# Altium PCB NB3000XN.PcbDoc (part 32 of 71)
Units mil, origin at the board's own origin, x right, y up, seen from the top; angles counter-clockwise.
Board outline 9527.56 x 6929.77 mil, 6 copper layers (Top Layer, GND+SHIELD, MidLayer1, MidLayer2, P2 - 3V3+5V0, Bottom Layer), stack 62.375 mil thick; 832 components, 1027 nets, 4655 pads, 4981 vias.
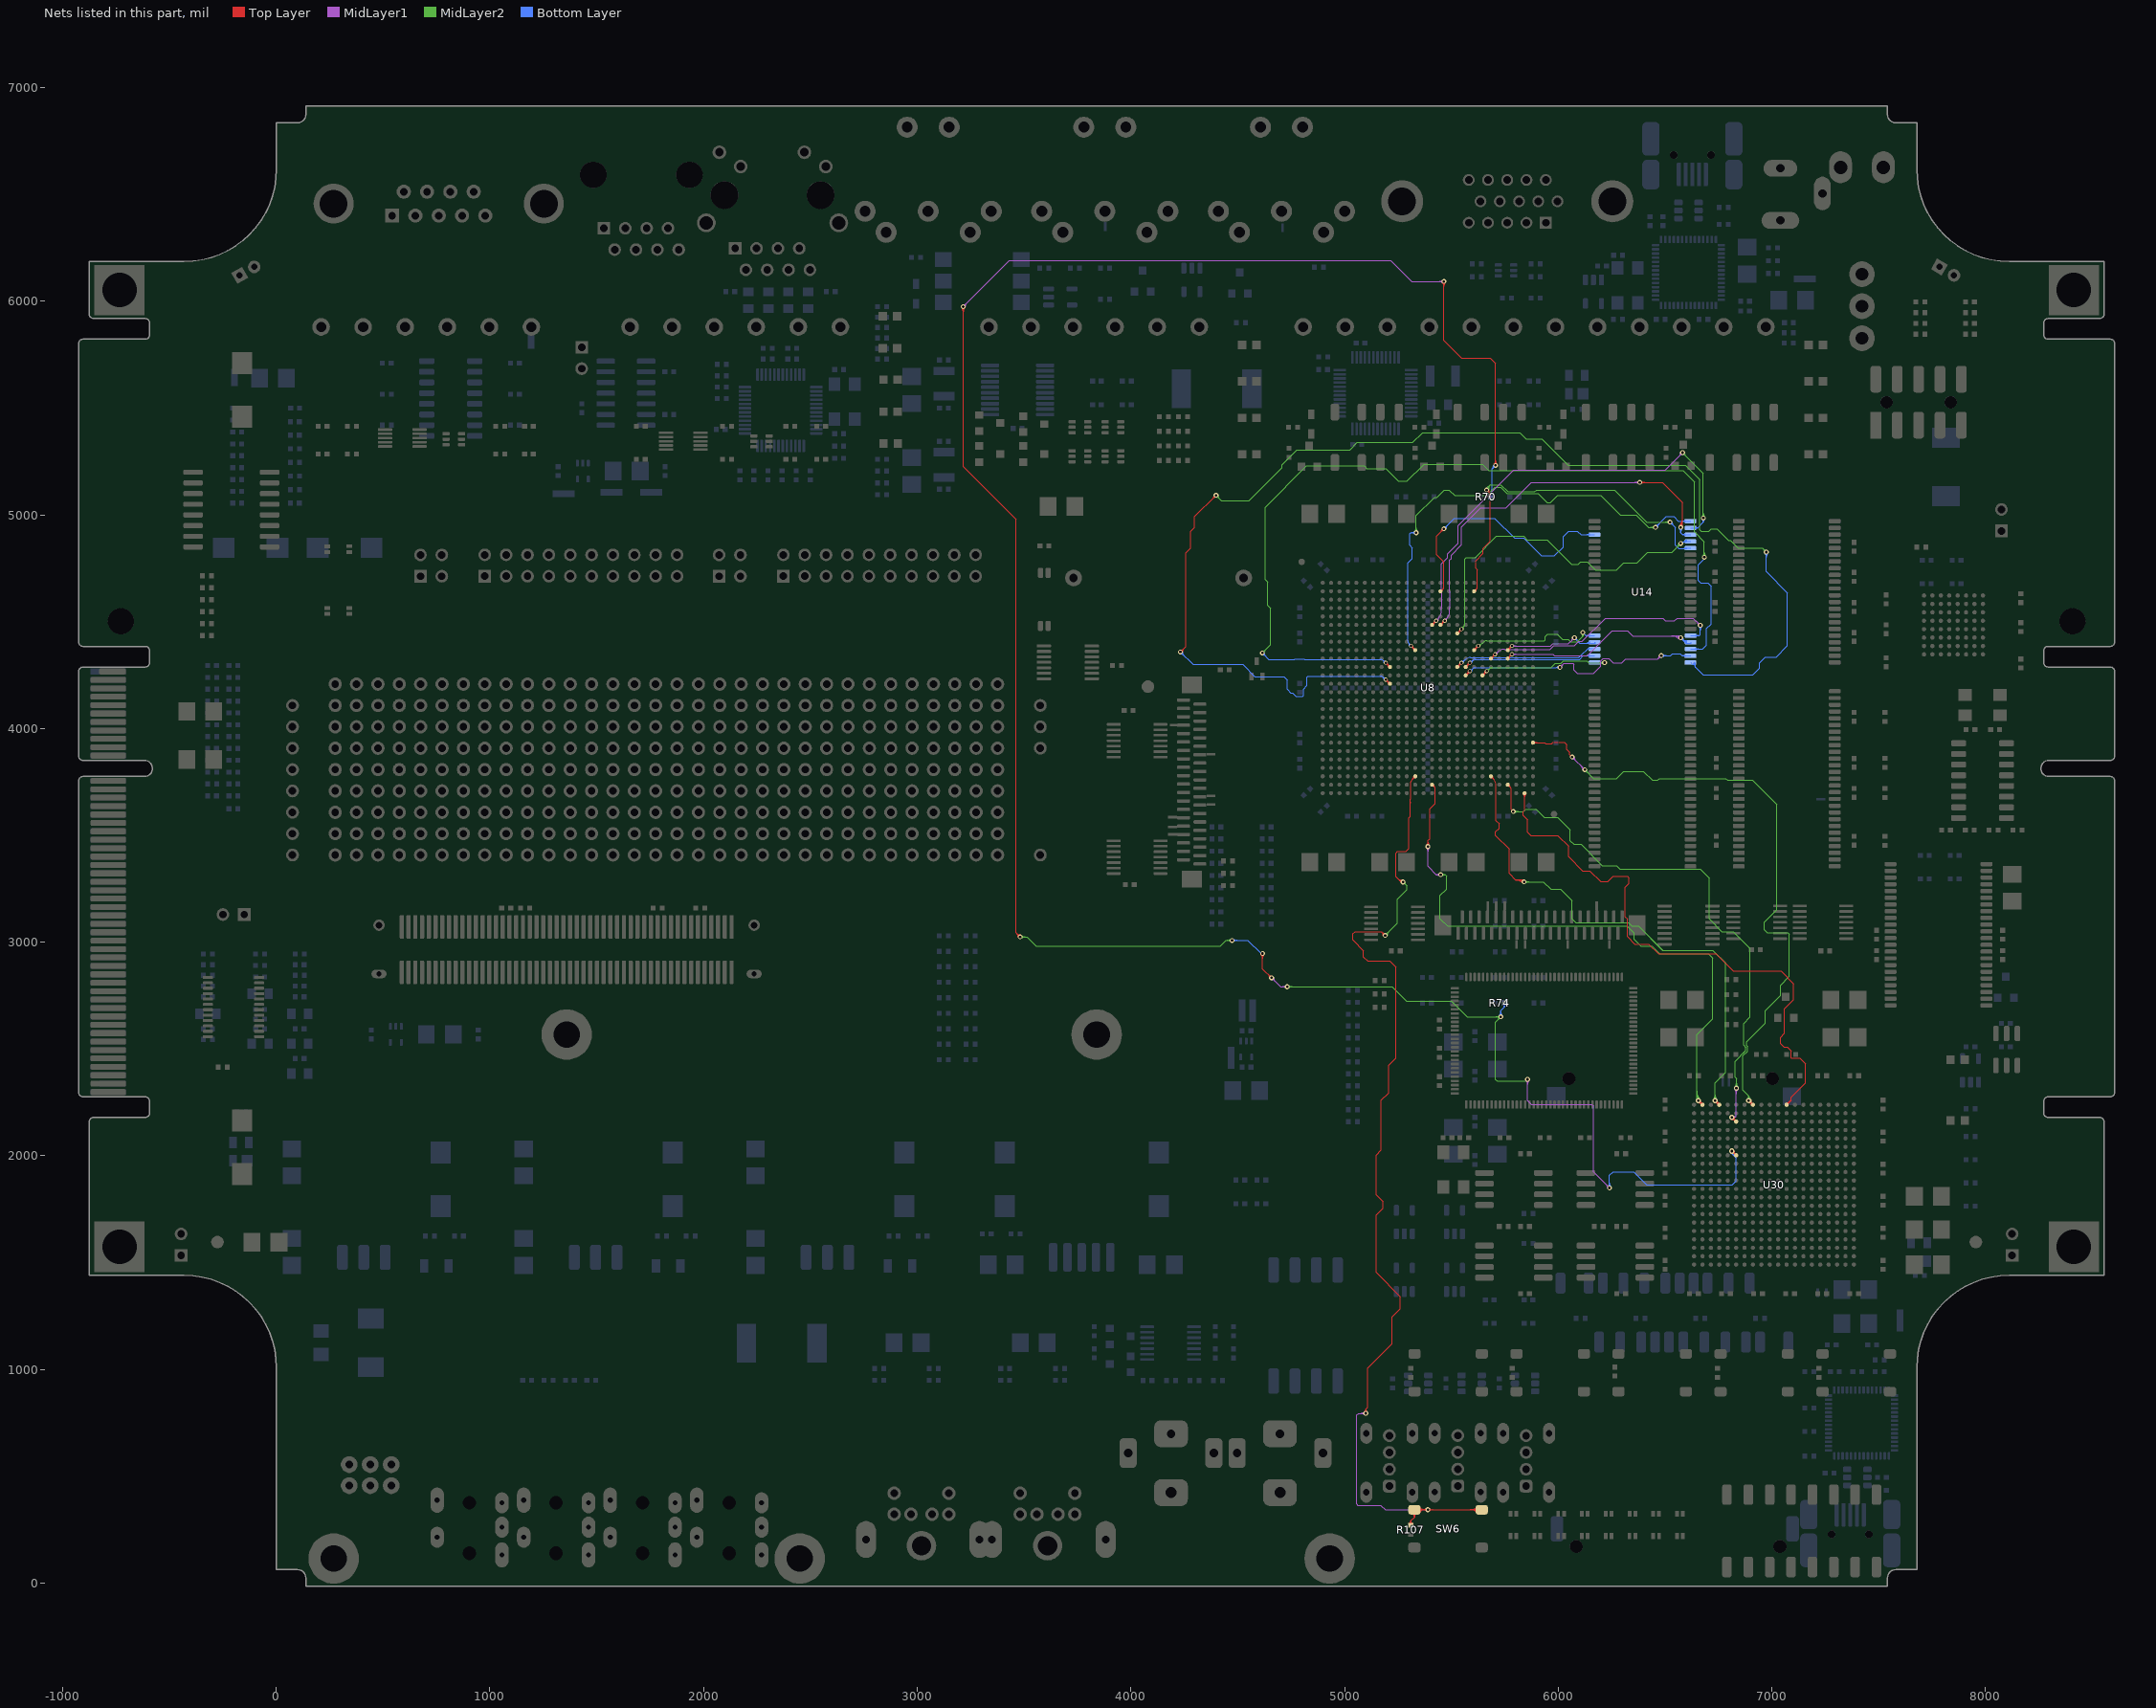
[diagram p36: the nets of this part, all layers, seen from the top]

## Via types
v1: diameter 23, hole 11.81, Top Layer to Bottom Layer, 3672 vias
v2: diameter 26, hole 11.81, Top Layer to Bottom Layer, 461 vias
v3: diameter 19, hole 11.81, Top Layer to Bottom Layer, tented both sides, 396 vias
v4: diameter 23.62, hole 11.81, Top Layer to Bottom Layer, 288 vias
v5: diameter 20, hole 11.81, Top Layer to Bottom Layer, 91 vias
v6: diameter 23, hole 11.81, Top Layer to Bottom Layer, tented both sides, 50 vias
v7: diameter 31, hole 11.81, Top Layer to Bottom Layer, 15 vias
v8: diameter 27.56, hole 11.81, Top Layer to Bottom Layer, tented both sides, 4 vias
v9: diameter 29, hole 11.81, Top Layer to Bottom Layer, 3 vias
v10: diameter 21, hole 11.81, Top Layer to Bottom Layer, 1 vias

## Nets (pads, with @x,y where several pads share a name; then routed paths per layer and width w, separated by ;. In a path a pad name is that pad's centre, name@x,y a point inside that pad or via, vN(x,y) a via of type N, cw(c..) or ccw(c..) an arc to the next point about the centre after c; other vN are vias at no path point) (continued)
DB_PROGRAM.PROGRAM: R70.1 R74.1 U30.R7 | length 12775.2
  Top Layer w4: v1@3208.47,5968.32 cw(c3192.26,5952.11) 3215.19,5952.11 cw(c3238.13,5952.11) v1@3221.91,5968.32 ; v1@3211.3,5971.15 cw(c3201.91,5961.76) 3215.19,5961.76 cw(c3228.47,5961.76) v1@3219.08,5971.15 ; v1(3215.19,5975.04) 3215.19,5224.81 3461.52,4978.48 3461.52,3045.37 v1(3481.86,3025.04) ; v1@3472.36,3025.04 ccw(c3449.42,3025.04) 3465.64,3041.26 ccw(c3481.86,3057.48) v1@3481.86,3034.54 ; v1@3476.36,3025.04 ccw(c3463.08,3025.04) 3472.47,3034.43 ccw(c3481.86,3043.82) v1@3481.86,3030.54 ; v1@4609.81,2940.66 cw(c4593.59,2924.44) 4616.52,2924.44 cw(c4639.46,2924.44) v1@4623.24,2940.66 ; v1@4612.64,2943.49 cw(c4603.25,2934.1) 4616.52,2934.1 cw(c4629.8,2934.1) v1@4620.41,2943.49 ; v1@4615.19,2947.37 v1(4616.52,2947.37) 4616.52,2875.37 v1(4658.52,2833.37) ; v1@4649.02,2833.37 ccw(c4626.09,2833.37) 4642.31,2849.59 ccw(c4658.52,2865.81) v1@4658.52,2842.87 ; v1@4653.02,2833.37 ccw(c4639.75,2833.37) 4649.14,2842.76 ccw(c4658.52,2852.15) v1@4658.52,2838.87 ; v1@5458.47,6085.99 cw(c5442.26,6069.77) 5465.19,6069.77 cw(c5488.13,6069.77) v1@5471.91,6085.99 ; v1@5461.3,6088.82 cw(c5451.91,6079.43) 5465.19,6079.43 cw(c5478.47,6079.43) v1@5469.08,6088.82 ; v1(5465.19,6092.71) 5465.19,5816.71 5548.52,5733.37 5681.86,5733.37 5706.86,5708.37 v1(5706.86,5232.04) ; v1@5700.14,5238.76 ccw(c5683.92,5254.98) 5706.86,5254.98 ccw(c5729.79,5254.98) v1@5713.57,5238.76 ; v1@5702.97,5235.93 ccw(c5693.58,5245.32) 5706.86,5245.32 ccw(c5720.14,5245.32) v1@5710.75,5235.93
  Top Layer w8: v2@6813.15,2013.48 cw(c6813.15,1991.75) 6828.51,2007.12 cw(c6843.88,2022.48) v2@6822.15,2022.48 ; v2(6813.15,2022.48) U30.R7@6832.83,2002.8 ; U30.R7@6826.99,2002.8 ccw(c6812.89,2002.8) 6822.86,2012.77 ccw(c6832.83,2022.74) U30.R7@6832.83,2008.64
  MidLayer1 w4: v1(3215.19,5975.04) 3431.86,6191.71 5215.19,6191.71 5315.19,6091.71 5465.19,6091.71 v1(5465.19,6092.71) ; v1@3215.19,5980.54 ccw(c3215.19,5993.82) 3224.58,5984.43 ccw(c3233.97,5975.04) v1@3220.69,5975.04 ; v1@3215.19,5984.54 ccw(c3215.19,6007.48) 3231.41,5991.26 ccw(c3247.63,5975.04) v1@3224.69,5975.04 ; v1@4658.52,2823.87 cw(c4658.52,2800.94) 4674.74,2817.16 cw(c4690.96,2833.37) v1@4668.02,2833.37 ; v1@4658.52,2827.87 cw(c4658.52,2814.6) 4667.91,2823.99 cw(c4677.3,2833.37) v1@4664.02,2833.37 ; v1(4658.52,2833.37) 4700.19,2791.71 v1(4731.86,2791.71) ; v1@4725.14,2784.99 ccw(c4708.92,2768.77) 4708.92,2791.71 ccw(c4708.92,2814.64) v1@4725.14,2798.43 ; v1@4727.97,2787.82 ccw(c4718.58,2778.43) 4718.58,2791.71 ccw(c4718.58,2804.99) v1@4727.97,2795.6 ; 5439.84,6091.71 ccw(c5439.84,6118.06) v1@5458.47,6099.43 ; 5444.67,6091.71 cw(c5444.67,6072.19) v1@5458.47,6085.99 ; 5449.5,6091.71 ccw(c5449.5,6108.4) v1@5461.3,6096.6 ; v1@5850.14,2351.66 cw(c5833.92,2335.44) 5856.86,2335.44 cw(c5879.79,2335.44) v1@5863.57,2351.66 ; v1@5852.97,2354.49 cw(c5843.58,2345.1) 5856.86,2345.1 cw(c5870.14,2345.1) v1@5860.75,2354.49 ; v1(5856.86,2358.37) 5856.86,2258.37 5873.52,2241.71 6156.86,2241.71 6165.19,2233.37 6165.19,1925.04 v1(6240.19,1850.04) ; v1@6230.69,1850.04 ccw(c6207.76,1850.04) 6223.97,1866.26 ccw(c6240.19,1882.48) v1@6240.19,1859.54 ; v1@6234.69,1850.04 ccw(c6221.41,1850.04) 6230.8,1859.43 ccw(c6240.19,1868.82) v1@6240.19,1855.54
  MidLayer2 w4: v1(3481.86,3025.04) 3515,3025.04 3557.33,2982.71 4419.33,2982.71 4445,3008.37 v1(4473.52,3008.37) ; v1@3485.75,3021.15 cw(c3495.14,3011.76) 3495.14,3025.04 cw(c3495.14,3038.32) v1@3485.75,3028.93 ; v1@3488.57,3018.32 cw(c3504.79,3002.11) 3504.79,3025.04 cw(c3504.79,3047.98) v1@3488.57,3031.76 ; v1@4466.81,3001.66 ccw(c4450.59,2985.44) 4450.59,3008.37 ccw(c4450.59,3031.31) v1@4466.81,3015.09 ; v1@4469.64,3004.49 ccw(c4460.25,2995.1) 4460.25,3008.37 ccw(c4460.25,3021.65) v1@4469.64,3012.26 ; v1(4731.86,2791.71) 5223.52,2791.71 5290.52,2724.71 5500.29,2724.71 5575.29,2649.71 5683.67,2649.71 5685,2651.04 v1(5731.86,2651.04) 5706.86,2626.04 5706.86,2358.14 5715,2350 5848.48,2350 v1(5856.86,2358.37) ; v1@4735.75,2787.82 cw(c4745.14,2778.43) 4745.14,2791.71 cw(c4745.14,2804.99) v1@4735.75,2795.6 ; v1@4738.57,2784.99 cw(c4754.79,2768.77) 4754.79,2791.71 cw(c4754.79,2814.64) v1@4738.57,2798.43 ; v1@5722.36,2651.04 cw(c5699.42,2651.04) 5715.64,2634.82 cw(c5731.86,2618.61) v1@5731.86,2641.54 ; v1@5725.14,2644.32 ccw(c5708.92,2628.11) 5708.92,2651.04 ccw(c5708.92,2673.98) v1@5725.14,2657.76 ; v1@5726.36,2651.04 cw(c5713.08,2651.04) 5722.47,2641.65 cw(c5731.86,2632.26) v1@5731.86,2645.54 ; v1@5727.97,2647.15 ccw(c5718.58,2637.76) 5718.58,2651.04 ccw(c5718.58,2664.32) v1@5727.97,2654.93
  Bottom Layer w4: v1(4473.52,3008.37) 4547.19,3008.37 4608.19,2947.37 v1(4616.52,2947.37) ; v1@4477.41,3004.49 cw(c4486.8,2995.1) 4486.8,3008.37 cw(c4486.8,3021.65) v1@4477.41,3012.26 ; v1@4480.24,3001.66 cw(c4496.46,2985.44) 4496.46,3008.37 cw(c4496.46,3031.31) v1@4480.24,3015.09 ; R70.1@5677.09,5092.08 ccw(c5645.47,5123.7) 5690.19,5123.7 ; R70.1@5679.92,5089.25 ccw(c5655.13,5114.05) 5690.19,5114.05 ; R70.1@5682.75,5086.42 ccw(c5664.78,5104.39) 5690.19,5104.39 ; R70.1@5683.68,5085 5683.68,5083.37 5690.19,5083.37 5690.19,5085 5690.19,5215.37 v1(5706.86,5232.04) ; v1@5697.36,5232.04 cw(c5674.42,5232.04) 5690.64,5215.82 cw(c5706.86,5199.61) v1@5706.86,5222.54 ; v1@5701.36,5232.04 cw(c5688.08,5232.04) 5697.47,5222.65 cw(c5706.86,5213.26) v1@5706.86,5226.54 ; v1@5725.14,2657.76 ccw(c5708.92,2673.98) 5731.86,2673.98 ccw(c5754.79,2673.98) v1@5738.57,2657.76 ; v1@5727.97,2654.93 ccw(c5718.58,2664.32) 5731.86,2664.32 ccw(c5745.14,2664.32) v1@5735.75,2654.93 ; v1(5731.86,2651.04) 5731.86,2680.05 5748.18,2696.37 ; R74.1@5742.76,2706.93 cw(c5735.2,2696.38) 5748.18,2696.38 ; R74.1@5748.18,2715 5748.18,2696.37 ; R74.1@5753.61,2706.93 ccw(c5761.16,2696.38) 5748.18,2696.38 ; v1@6233.47,1856.76 ccw(c6217.26,1872.98) 6240.19,1872.98 ccw(c6263.13,1872.98) v1@6246.91,1856.76 ; v1@6236.3,1853.93 ccw(c6226.91,1863.32) 6240.19,1863.32 ccw(c6253.47,1863.32) v1@6244.08,1853.93 ; v1(6240.19,1850.04) 6240.19,1908.37 6256.86,1925.04 6353.86,1925.04 6415.19,1863.71 6815.19,1863.71 6832.86,1881.37 6832.86,1990.71 6815.19,2008.37 6815.19,2022.48 v2(6813.15,2022.48) ; v2@6812.24,2022.9 ccw(c6823.51,2017.64) 6814.72,2008.85 ; v2@6815.87,2021.21 ccw(c6829.01,2015.07) 6818.75,2004.81 ; v2@6819.49,2019.52 ccw(c6834.51,2012.5) 6822.79,2000.78 ; v2@6823.12,2017.82 ccw(c6840.01,2009.93) 6826.82,1996.74
DB_RESET: R107.2 SW6.1 SW6.2 U8.AD12 | length 5826.8
  Top Layer w4: v4@5094.05,802.8 ccw(c5084.9,814.81) 5100,814.81 ; v4(5100,795) 5100,814.81 ; v4@5105.95,802.8 cw(c5115.1,814.81) 5100,814.81 ; v1@5180.69,3031.71 ccw(c5157.76,3031.71) 5173.97,3047.93 ccw(c5190.19,3064.14) v1@5190.19,3041.21 ; v1@5184.69,3031.71 ccw(c5171.41,3031.71) 5180.8,3041.1 ccw(c5190.19,3050.49) v1@5190.19,3037.21 ; v1(5190.19,3031.71) 5171.86,3050.04 5050.04,3050.04 5040,3040 5040,3010 5089.52,2960.48 5089.52,2930 5107.52,2912 5211.69,2912 5240.19,2883.5 5240.19,2458.37 5206.86,2425.04 5206.86,2295 5172,2260.14 5172,2027 5147.86,2002.86 5147.86,1818.46 5180,1786.31 5180,1755 5147.86,1722.86 5147.86,1453.46 5260,1341.31 5260,1283.54 5222.69,1246.23 5222.69,1120.62 5107.81,1005.74 5107.81,822.62 5100,814.81 ; 5244.36,3302.54 ccw(c5271.79,3329.97) v1@5273.18,3291.2 ; 5250.85,3296.04 ccw(c5272.24,3317.43) v1@5273.33,3287.2 ; 5257.35,3289.55 ccw(c5272.69,3304.89) v1@5273.47,3283.21 ; v1(5273.52,3281.71) 5265.19,3281.71 5240.19,3306.71 5240.19,3416.71 5248.52,3425.04 5287.19,3425.04 5301.19,3439.04 5301.19,3557 5301.19,3582.31 5307.08,3588.21 5307.08,3651.25 ; R107.2@5303.87,278.2 ccw(c5292.05,291.71) 5310,291.71 ; R107.2@5306.5,275.19 ccw(c5299.76,282.9) 5310,282.9 ccw(c5320.24,282.9) R107.2@5313.5,275.19 ; R107.2@5310,271.18 5310,291.71 ; R107.2@5316.13,278.2 cw(c5327.95,291.71) 5310,291.71 ; SW6.1@5317.21,325.64 cw(c5307.93,308.84) 5327.13,308.84 ; SW6.1@5319.15,329.14 cw(c5311.67,315.61) 5327.13,315.61 cw(c5342.58,315.62) SW6.1@5335.11,329.14 ; U8.AD12@5323.6,3776.61 cw(c5305.88,3776.61) 5318.41,3764.08 ; U8.AD12@5330.94,3769.27 ccw(c5330.94,3751.55) 5318.41,3764.08 ; SW6.1@5337.04,325.64 ccw(c5346.33,308.84) 5327.13,308.84 ; SW6.1@5341.96,334.74 cw(c5363.3,313.4) 5363.3,343.58 cw(c5363.3,373.76) SW6.1@5341.96,352.42 ; SW6.1@5344.79,331.92 cw(c5372.96,303.75) 5372.96,343.58 cw(c5372.96,383.42) SW6.1@5344.79,355.25 ; SW6.1@5347.62,329.09 cw(c5382.62,294.09) 5382.62,343.58 cw(c5382.62,393.07) SW6.1@5347.62,358.08 ; v4@5383.06,336.65 ccw(c5366.31,319.9) 5366.31,343.58 ccw(c5366.31,367.27) v4@5383.06,350.52 ; v4@5385.89,339.47 ccw(c5375.97,329.55) 5375.97,343.58 ccw(c5375.97,357.61) v4@5385.89,347.69 ; v4@5394.11,339.47 cw(c5404.03,329.55) 5404.03,343.58 cw(c5404.03,357.61) v4@5394.11,347.69 ; v4@5396.94,336.65 cw(c5413.69,319.9) 5413.69,343.58 cw(c5413.69,367.27) v4@5396.94,350.52 ; SW6.2@5621.98,329.09 ccw(c5586.99,294.09) 5586.99,343.58 ccw(c5586.99,393.07) SW6.2@5621.98,358.08 ; SW6.2@5624.81,331.92 ccw(c5596.65,303.75) 5596.65,343.58 ccw(c5596.65,383.42) SW6.2@5624.81,355.25 ; SW6.2@5627.64,334.74 ccw(c5606.3,313.4) 5606.3,343.58 ccw(c5606.3,373.76) SW6.2@5627.64,352.42 ; SW6.2@5642.48,343.58 v4(5390,343.58) SW6.1@5327.13,343.58 5327.13,308.83 ; 5307.08,3651.25 5307.08,3657 ; 5307.08,3651.25 5307.08,3655.26 5307.08,3657 ; 5307.08,3657 5307.08,3660 5307.08,3670 5307.08,3736.73 cw(c5345.76,3736.73) 5318.41,3764.08 ; 5310,291.71 5327.13,308.83
  MidLayer1 w4: v4@5093.06,788.06 ccw(c5076.31,771.31) 5076.31,795 ccw(c5076.31,818.69) v4@5093.06,801.94 ; v4@5095.89,790.89 ccw(c5085.97,780.97) 5085.97,795 ccw(c5085.97,809.03) v4@5095.89,799.11 ; v4(5100,795) 5065,795 5056.19,786.19 5056.19,370.12 5061.31,365 5170,365 5191.42,343.58 v4(5390,343.58) ; v4@5383.06,336.65 ccw(c5366.31,319.9) 5366.31,343.58 ccw(c5366.31,367.27) v4@5383.06,350.52 ; v4@5385.89,339.47 ccw(c5375.97,329.55) 5375.97,343.58 ccw(c5375.97,357.61) v4@5385.89,347.69
  MidLayer2 w4: v1(5190.19,3031.71) 5248.52,3090.04 5248.52,3202.1 5292.05,3245.62 5292.05,3263.18 v1(5273.52,3281.71) ; v1@5190.19,3037.21 ccw(c5190.19,3050.49) 5199.58,3041.1 ccw(c5208.97,3031.71) v1@5195.69,3031.71 ; v1@5190.19,3041.21 ccw(c5190.19,3064.14) 5206.41,3047.93 ccw(c5222.63,3031.71) v1@5199.69,3031.71 ; v1@5273.52,3272.21 cw(c5273.52,3249.27) 5289.74,3265.49 cw(c5305.96,3281.71) v1@5283.02,3281.71 ; v1@5273.52,3276.21 cw(c5273.52,3262.93) 5282.91,3272.32 cw(c5292.3,3281.71) v1@5279.02,3281.71
DB_SPI.CLK: U8.AE14 U30.W1 | length 3224.2
  Top Layer w4: v1@5383.47,3454.43 ccw(c5363.6,3474.3) 5391.7,3474.3 ; v1@5386.3,3451.6 ccw(c5373.26,3464.64) 5391.7,3464.64 ; v1(5390.19,3447.71) 5391.7,3449.22 5391.7,3475.86 5399.7,3483.86 5399.7,3624.49 5425.19,3649.98 5425.19,3660 5425.19,3670 5425.19,3717.53 ccw(c5415.04,3717.53) 5422.22,3724.71 ; 5391.7,3466.99 ccw(c5409.47,3466.99) v1@5396.91,3454.43 ; U8.AE14@5409.69,3729.9 cw(c5409.69,3712.17) 5422.22,3724.71 ; U8.AE14@5417.03,3737.24 ccw(c5434.75,3737.24) 5422.22,3724.71
  Top Layer w8: v2@6655.67,2249.7 cw(c6655.67,2227.97) 6671.03,2243.34 cw(c6686.4,2258.7) v2@6664.67,2258.7 ; v2(6655.67,2258.7) U30.W1@6675.35,2239.02 ; U30.W1@6669.51,2239.02 ccw(c6655.41,2239.02) 6665.38,2248.99 ccw(c6675.35,2258.96) U30.W1@6675.35,2244.86
  MidLayer1 w4: v1@5383.47,3440.99 cw(c5367.26,3424.77) 5390.19,3424.77 cw(c5413.13,3424.77) v1@5396.91,3440.99 ; v1@5386.3,3443.82 cw(c5376.91,3434.43) 5390.19,3434.43 cw(c5403.47,3434.43) v1@5394.08,3443.82 ; v1(5390.19,3447.71) 5390.19,3355.06 5429.21,3316.04 ; 5437.8,3316.04 ccw(c5437.8,3326.38) v1@5445.72,3319.73 ; 5438.08,3316.04 cw(c5438.08,3305.74) v1@5445.8,3312.55 ; v1@5442.65,3322.3 cw(c5429.21,3333.6) 5429.21,3316.04 ; v1@5442.8,3309.91 ccw(c5429.21,3297.91) 5429.21,3316.04 ; v1(5449.93,3316.19) 5456.04,3316.19 5456.19,3316.04 5429.21,3316.04
  MidLayer2 w4: v1(5449.93,3316.19) v1@5456.04,3316.19 ; v1@5454.05,3312.55 cw(c5462.12,3305.42) 5462.12,3316.19 cw(c5462.12,3326.97) v1@5454.05,3319.83 ; v1@5456.86,3316.71 v1@5456.34,3316.19 ; v1@5457.05,3309.9 cw(c5471,3297.58) 5471,3316.19 ; v1@5457.05,3322.48 ccw(c5471,3334.81) 5471,3316.19 ; 6322.21,3075.04 6355.96,3041.29 6355.96,3013.6 6386.86,2982.71 6438.94,2982.71 6475.27,2946.37 6702.19,2946.37 6723.52,2925.04 6723.52,2641.71 6648.52,2566.71 6648.52,2258.69 v2(6655.67,2258.7) ; 6323.52,3073.71 6322.19,3075.04 5481.86,3075.04 5447.86,3109.04 5447.86,3195 5447.86,3219.02 5477.19,3248.35 5477.19,3252.71 5477.19,3270 5477.19,3310 5471,3316.19 ; 6648.52,2273.54 ccw(c6670.51,2273.54) v2@6654.96,2257.99 ; 6648.52,2283.19 ccw(c6680.16,2283.19) v2@6657.79,2260.82 ; 6648.52,2292.85 ccw(c6689.82,2292.85) v2@6660.62,2263.65 ; 6648.52,2302.51 ccw(c6699.48,2302.51) v2@6663.45,2266.48 ; v1@5456.04,3316.19 5456.19,3316.04 v1@5456.34,3316.19 ; v1@5456.04,3316.19 v1@5456.34,3316.19 ; v1@5456.34,3316.19 5471,3316.19
DB_SPI.DIN: U8.Y26 U30.N1 | length 3334.4
  Top Layer w4: U8.Y26@5882.13,3934.09 5910,3934.09 5920,3934.09 5937.74,3934.09 5941.84,3930 5969.68,3930 5974.83,3935.15 6029.42,3935.15 6040.02,3924.54 6040.02,3902.83 6053.5,3889.36 6053.5,3878.4 v1(6065.19,3866.71) ; U8.Y26@5887.43,3928.79 cw(c5900.23,3915.99) 5900.23,3934.09 cw(c5900.23,3952.2) U8.Y26@5887.43,3939.4 ; 5899.85,3934.09 ccw(c5899.85,3916.37) 5887.32,3928.9 cw(c5899.85,3916.37) 5899.85,3934.09 ; 5899.85,3934.09 cw(c5899.85,3951.82) 5887.32,3939.29 ccw(c5899.85,3951.82) 5899.85,3934.09
  Top Layer w8: v2@6891.89,2249.7 cw(c6891.89,2227.97) 6907.25,2243.34 cw(c6922.62,2258.7) v2@6900.89,2258.7 ; v2(6891.89,2258.7) U30.N1@6911.57,2239.02 ; U30.N1@6905.73,2239.02 ccw(c6891.63,2239.02) 6901.6,2248.99 ccw(c6911.57,2258.96) U30.N1@6911.57,2244.86
  MidLayer1 w4: v1@6065.19,3857.21 cw(c6065.19,3834.27) 6081.41,3850.49 cw(c6097.63,3866.71) v1@6074.69,3866.71 ; v1@6065.19,3861.21 cw(c6065.19,3847.93) 6074.58,3857.32 cw(c6083.97,3866.71) v1@6070.69,3866.71 ; v1(6065.19,3866.71) v1(6124.52,3807.37) ; v1@6115.02,3807.37 ccw(c6092.09,3807.37) 6108.31,3823.59 ccw(c6124.52,3839.81) v1@6124.52,3816.87 ; v1@6119.02,3807.37 ccw(c6105.75,3807.37) 6115.14,3816.76 ccw(c6124.52,3826.15) v1@6124.52,3812.87
  MidLayer2 w4: v1@6124.52,3797.87 cw(c6124.52,3774.94) 6140.74,3791.16 cw(c6156.96,3807.37) v1@6134.02,3807.37 ; v1@6124.52,3801.87 cw(c6124.52,3788.6) 6133.91,3797.99 cw(c6143.3,3807.37) v1@6130.02,3807.37 ; v1(6124.52,3807.37) 6165.19,3766.71 6273.52,3766.71 6306.86,3800.04 6398.52,3800.04 6440.19,3758.37 6465.19,3758.37 6473.52,3766.71 6784.23,3766.71 6792.56,3758.37 6909.23,3758.37 7023.52,3644.08 7023.52,3610 7023.52,3151.04 6965.19,3092.71 6965.19,3058.37 6978.56,3045 7075.52,3045 7082.52,3038 7082.52,2840.31 7040.19,2797.98 7040.19,2750.19 6970,2680 6970,2621.52 6881.86,2533.37 6881.86,2515.44 6886.69,2510.6 6886.69,2489.48 6865.19,2467.98 6865.19,2404.81 ; 6865,2405 6865.19,2404.81 ; v2@6884.99,2267.27 ccw(c6873.4,2281.67) 6891.89,2281.67 ; v2@6887.5,2264.15 ccw(c6880.12,2273.32) 6891.89,2273.32 ccw(c6903.66,2273.32) v2@6896.28,2264.15 ; v2@6890.19,2258.7 v2(6891.89,2258.7) 6891.89,2281.68 ; v2@6898.79,2267.27 cw(c6910.38,2281.67) 6891.89,2281.67 ; 6865.19,2404.81 6865.19,2308.37 6891.89,2281.68
DB_SPI.DOUT: U8.AD21 U30.U1 | length 2953.7
  Top Layer w4: 5809.74,3291.71 cw(c5809.74,3258.53) v1@5835.86,3278.98 ; 5817.95,3291.71 cw(c5817.95,3264.96) v1@5839.01,3281.45 ; 5826.16,3291.71 cw(c5826.16,3271.39) v1@5842.16,3283.92 ; v1@5832.71,3276.52 ccw(c5801.53,3252.1) 5801.53,3291.71 ; v1(5840.19,3282.37) 5830.86,3291.71 5801.52,3291.71 ; 5697.81,3764.08 cw(c5670.46,3736.73) 5709.14,3736.73 ; 5697.81,3764.08 cw(c5670.46,3736.73) 5709.14,3736.73 ; 5697.81,3764.08 cw(c5710.34,3776.61) 5692.62,3776.61 ccw(c5710.34,3776.61) 5697.81,3764.08 ; 5697.81,3764.08 ccw(c5685.28,3751.55) 5685.28,3769.27 cw(c5685.28,3751.55) 5697.81,3764.08 ; 5709.14,3736.73 5709.14,3670 5709.14,3660 5709.14,3598 5709.14,3589.43 5709.14,3569.39 5723.52,3555 5723.52,3533.37 5707.19,3517.04 5707.19,3499.71 5771.19,3435.71 5771.19,3322.04 5801.52,3291.71
  Top Layer w8: v2@6734.41,2249.7 cw(c6734.41,2227.97) 6749.77,2243.34 cw(c6765.14,2258.7) v2@6743.41,2258.7 ; v2(6734.41,2258.7) U30.U1@6754.09,2239.02 ; U30.U1@6748.25,2239.02 ccw(c6734.15,2239.02) 6744.12,2248.99 ccw(c6754.09,2258.96) U30.U1@6754.09,2244.86
  MidLayer2 w4: v1(5840.19,3282.37) 5930.86,3282.37 5965.19,3248.04 6010.65,3248.04 6065.19,3193.5 6065.19,3108.37 6081.86,3091.71 6328.17,3091.71 6344.84,3075.04 6376.27,3075.04 ; v1@5844.08,3278.49 cw(c5853.47,3269.1) 5853.47,3282.37 cw(c5853.47,3295.65) v1@5844.08,3286.26 ; v1@5846.91,3275.66 cw(c5863.13,3259.44) 5863.13,3282.37 cw(c5863.13,3305.31) v1@5846.91,3289.09 ; v2@6726.63,2266.48 ccw(c6707.85,2285.26) 6734.41,2285.26 ccw(c6760.97,2285.26) v2@6742.19,2266.48 ; v2@6729.46,2263.65 ccw(c6717.51,2275.6) 6734.41,2275.6 ccw(c6751.31,2275.6) v2@6739.36,2263.65 ; v2@6740.19,2258.7 v2(6734.41,2258.7) 6734.41,2341.55 6782.86,2390 6782.86,2903.04 6723.52,2962.37 6489.78,2962.37 ; 6376.27,3075.04 6377.11,3075.04 6489.78,2962.37 ; 6376.27,3075.04 6488.94,2962.37 6489.78,2962.37
DB_SPI.MODE: U8.AF25 U30.J1 | length 2751.2
  Top Layer w4: U8.AF25@5837.45,3692.57 cw(c5824.65,3679.77) 5842.76,3679.77 cw(c5860.86,3679.77) U8.AF25@5848.06,3692.57 ; U8.AF25@5837.56,3692.68 cw(c5825.03,3680.15) 5842.76,3680.15 cw(c5860.48,3680.15) U8.AF25@5847.95,3692.68 ; U8.AF25@5842.76,3697.87 5842.76,3670 5842.76,3660 5842.76,3617.94 5837.19,3612.38 5837.19,3592.09 5857.02,3572.25 5857.02,3519.29 5857.02,3515.84 5872.82,3500.04 5998.52,3500.04 6048.52,3450.04 6048.52,3400.04 6115.19,3333.37 6148.52,3333.37 6198.52,3283.37 6231.86,3283.37 6256.86,3308.37 6323.52,3308.37 6331.86,3300.04 6331.86,3275.04 6313.19,3256.37 6313.19,3118.71 6323.52,3108.37 6323.52,3026.71 6358.52,2991.71 6423.29,2991.71 6470,2945 6740,2945 6820.3,2864.7 7043.2,2864.7 7102,2805.9 7102,2730.18 7060,2688.18 7060,2574.81 7040.19,2555 7040.19,2525.04 7056.86,2508.37 7073.52,2508.37 7090.19,2491.71 7090.19,2458.71 7091.86,2457.04 7131.86,2457.04 7156.86,2432.04 7156.86,2341.71 7090.19,2275.04 7090.19,2259.71 7088.86,2258.37
  Top Layer w8: U30.J1@7069.06,2239.02 7088.74,2258.7 ; U30.J1@7069.06,2244.86 ccw(c7069.06,2258.96) 7079.03,2248.99 ccw(c7089,2239.02) U30.J1@7074.9,2239.02
DB_SPI.SEL: U8.AE23 U30.R3 | length 2854.8
  Top Layer w4: v1@5790.19,3616.71 v1(5790.19,3611.71) 5779.52,3622.37 5779.52,3660 5779.52,3670 5779.52,3717.53 ; 5776.55,3724.71 cw(c5769.37,3717.53) 5779.52,3717.53 ; 5776.55,3724.71 cw(c5769.37,3717.53) 5779.52,3717.53 ; 5776.55,3724.71 ccw(c5764.02,3712.17) 5764.02,3729.9 cw(c5764.02,3712.17) 5776.55,3724.71 ; 5776.55,3724.71 cw(c5789.08,3737.24) 5771.36,3737.24 ccw(c5789.08,3737.24) 5776.55,3724.71
  Top Layer w8: v2@6813.15,2170.96 cw(c6813.15,2149.23) 6828.51,2164.6 cw(c6843.88,2179.96) v2@6822.15,2179.96 ; v2(6813.15,2179.96) U30.R3@6832.83,2160.28 ; U30.R3@6826.99,2160.28 ccw(c6812.89,2160.28) 6822.86,2170.25 ccw(c6832.83,2180.22) U30.R3@6832.83,2166.12
  MidLayer1 w4: v2(6813.15,2179.96) 6813.15,2183.37 6830.86,2183.37 ; v2@6820,2178.54 cw(c6825.94,2177.31) 6825.94,2183.37 ; v2@6821.11,2187.55 ccw(c6830.86,2196.83) 6830.86,2183.37 ; v2@6823.92,2177.73 cw(c6830.86,2176.29) 6830.86,2183.37 ; v1@6827.47,2309.99 cw(c6815.28,2297.79) 6832.52,2297.79 ; 6832.52,2289.75 cw(c6861.15,2289.75) v1@6840.91,2309.99 ; 6832.52,2299.41 cw(c6851.49,2299.41) v1@6838.08,2312.82 ; v1(6834.19,2316.71) 6832.52,2315.04 6832.52,2185.04 6830.86,2183.37
  MidLayer2 w4: v1(5790.19,3611.71) 5836.52,3611.71 5847.62,3622.81 5895.75,3622.81 5935.19,3583.37 5998.52,3583.37 6056.86,3525.04 6056.86,3475.04 6073.52,3458.37 6106.86,3458.37 6206.86,3358.37 6273.52,3358.37 6289.86,3342.04 6665.19,3342.04 6706.86,3300.37 6706.86,3108.37 6765.19,3050.04 6819.86,3050.04 6898.52,2971.37 6898.52,2650.04 6868.44,2619.96 6868.44,2517.54 6878.69,2507.29 6878.69,2492.79 ; v1@5794.08,3607.82 cw(c5803.47,3598.43) 5803.47,3611.71 cw(c5803.47,3624.99) v1@5794.08,3615.6 ; v1@5796.91,3604.99 cw(c5813.13,3588.77) 5813.13,3611.71 cw(c5813.13,3634.64) v1@5796.91,3618.43 ; v1@6827.47,2323.43 ccw(c6811.26,2339.64) 6834.19,2339.64 ccw(c6857.13,2339.64) v1@6840.91,2323.43 ; v1@6830.3,2320.6 ccw(c6820.91,2329.99) 6834.19,2329.99 ccw(c6847.47,2329.99) v1@6838.08,2320.6 ; v1(6834.19,2316.71) 6834.19,2361.06 6827.5,2367.75 6827.5,2441.6 6878.69,2492.79 ; 6868.44,2482.54 6878.69,2492.79
DB_SRAM1.A0: U8.J12 U14.1 | length 2559.5
  Top Layer w4: v3(5311.26,4386.85) U8.J12@5330.94,4367.17 ; U8.J12@5323.44,4367.17 ccw(c5305.34,4367.17) 5318.14,4379.97 ccw(c5330.94,4392.77) U8.J12@5330.94,4374.67 ; U8.J12@5323.6,4367.17 ccw(c5305.88,4367.17) 5318.41,4379.7 ccw(c5330.94,4392.23) U8.J12@5330.94,4374.51 ; 5324.06,4374.05 cw(c5336.87,4386.85) 5318.76,4386.85 ccw(c5336.87,4386.85) 5324.06,4374.05 ; 5324.06,4374.05 ccw(c5311.26,4361.24) 5311.26,4379.35 cw(c5311.26,4361.24) 5324.06,4374.05
  MidLayer2 w4: v1@5328.81,4923.43 ccw(c5312.59,4939.64) 5335.52,4939.64 ccw(c5358.46,4939.64) v1@5342.24,4923.43 ; v1@5331.64,4920.6 ccw(c5322.25,4929.99) 5335.52,4929.99 ccw(c5348.8,4929.99) v1@5339.41,4920.6 ; v1(5335.52,4916.71) 5335.52,4996.37 5422.52,5083.37 5432.52,5083.37 5465.86,5116.71 5490.19,5116.71 5515.19,5091.71 5665.86,5091.71 5703.52,5129.37 5731.52,5129.37 5760.86,5100.04 5906.52,5100.04 5948.19,5058.37 5964.86,5058.37 5998.19,5091.71 6198.52,5091.71 6290.19,5000.04 6363.86,5000.04 6422.19,4941.71 v1(6455.52,4941.71) ; v1@6448.81,4934.99 ccw(c6432.59,4918.77) 6432.59,4941.71 ccw(c6432.59,4964.64) v1@6448.81,4948.43 ; v1@6451.64,4937.82 ccw(c6442.25,4928.43) 6442.25,4941.71 ccw(c6442.25,4954.99) v1@6451.64,4945.6
  Bottom Layer w4: 5299.87,4400.43 cw(c5309.8,4410.36) 5295.75,4410.36 5295.75,4503.9 5295.75,4710 5295.75,4720 5295.75,4774.6 5317.19,4796.04 5317.19,4845.71 5305.52,4857.37 5305.52,4911.37 5310.86,4916.71 v1(5335.52,4916.71) ; v3@5303.79,4387.5 ccw(c5285.75,4389.08) 5299.62,4400.72 ccw(c5313.49,4412.36) v3@5311.91,4394.32 ; v1@5328.81,4909.99 ccw(c5312.59,4893.77) 5312.59,4916.71 ccw(c5312.59,4939.64) v1@5328.81,4923.43 ; v1@5331.64,4912.82 ccw(c5322.25,4903.43) 5322.25,4916.71 ccw(c5322.25,4929.99) v1@5331.64,4920.6 ; v1(6455.52,4941.71) 6505.68,4991.87 6541.36,4991.87 6562.52,4970.71 U14.1@6619.41,4970.71 ; v1@6455.52,4947.21 ccw(c6455.52,4960.49) 6464.91,4951.1 ccw(c6474.3,4941.71) v1@6461.02,4941.71 ; v1@6455.52,4951.21 ccw(c6455.52,4974.14) 6471.74,4957.93 ccw(c6487.96,4941.71) v1@6465.02,4941.71 ; U14.1@6596.19,4965.05 ccw(c6582.54,4951.39) 6582.54,4970.71 ccw(c6582.54,4990.02) U14.1@6596.19,4976.37
DB_SRAM1.A1: U8.F14 U14.2 | length 2521.7
  Top Layer w4: U8.F14@5409.69,4485.28 v3(5429.37,4504.96) ; U8.F14@5409.69,4492.62 ccw(c5409.69,4510.34) 5422.22,4497.81 ccw(c5434.75,4485.28) U8.F14@5417.03,4485.28 ; U8.F14@5409.69,4492.78 ccw(c5409.69,4510.88) 5422.49,4498.08 ccw(c5435.29,4485.28) U8.F14@5417.19,4485.28 ; 5416.57,4492.16 cw(c5429.37,4479.35) 5429.37,4497.46 ccw(c5429.37,4479.35) 5416.57,4492.16 ; 5416.57,4492.16 ccw(c5403.76,4504.96) 5421.87,4504.96 cw(c5403.76,4504.96) 5416.57,4492.16
  MidLayer1 w4: v3@5428.72,4512.43 ccw(c5427.14,4530.47) 5441.01,4518.83 ; v3@5436.84,4505.61 cw(c5454.88,4507.19) 5441.01,4518.83 ; 5453.23,4581.77 5453.23,4567.84 ; v1@6572.36,5291.71 cw(c6549.42,5291.71) 6565.64,5275.49 cw(c6581.86,5259.27) v1@6581.86,5282.21 ; v1@6576.36,5291.71 cw(c6563.08,5291.71) 6572.47,5282.32 cw(c6581.86,5272.93) v1@6581.86,5286.21 ; v1(6581.86,5291.71) 6500.86,5210.71 5792.52,5210.71 5531.86,4950.04 5531.86,4867.32 5482.5,4817.96 5482.5,4800.68 5453.23,4771.42 5453.23,4724.74 5453.23,4720 5453.23,4710 5453.23,4661.38 5453.23,4641.96 5453.23,4567.84 ; 5441.01,4518.83 ccw(c5411.5,4548.34) 5453.23,4548.34 5453.23,4567.84
  MidLayer2 w4: v1@6581.86,5282.21 cw(c6581.86,5259.27) 6598.07,5275.49 cw(c6614.29,5291.71) v1@6591.36,5291.71 ; v1@6581.86,5286.21 cw(c6581.86,5272.93) 6591.25,5282.32 cw(c6600.64,5291.71) v1@6587.36,5291.71 ; v1(6581.86,5291.71) 6679.52,5194.04 v1(6679.52,4985.71) ; v1@6672.81,4992.43 ccw(c6656.59,5008.64) 6679.52,5008.64 ccw(c6702.46,5008.64) v1@6686.24,4992.43 ; v1@6675.64,4989.6 ccw(c6666.25,4998.99) 6679.52,4998.99 ccw(c6692.8,4998.99) v1@6683.41,4989.6
  Bottom Layer w4: U14.2@6619.41,4939.21 6653.52,4939.21 ; U14.2@6643.24,4934.24 cw(c6653.52,4926.08) 6653.52,4939.21 ; U14.2@6643.24,4944.18 ccw(c6653.52,4952.34) 6653.52,4939.21 ; v1@6673.38,4978.46 cw(c6662.17,4965.21) 6679.52,4965.21 ; v1@6675.97,4981.51 cw(c6669.48,4973.84) 6679.52,4973.84 cw(c6689.57,4973.84) v1@6683.08,4981.51 ; v1(6679.52,4985.71) 6679.52,4965.21 ; v1@6685.66,4978.46 ccw(c6696.88,4965.21) 6679.52,4965.21 ; 6653.52,4939.21 6679.52,4965.21
DB_SRAM1.A2: U8.F15 U14.3 | length 2305.8
  Top Layer w4: U8.F15@5449.06,4485.28 v3(5468.74,4504.96) ; U8.F15@5449.06,4492.62 ccw(c5449.06,4510.34) 5461.59,4497.81 ccw(c5474.12,4485.28) U8.F15@5456.4,4485.28 ; U8.F15@5449.06,4492.78 ccw(c5449.06,4510.88) 5461.86,4498.08 ccw(c5474.66,4485.28) U8.F15@5456.56,4485.28 ; v1(6381.86,5152.37) 6487.86,5152.37 6581.86,5058.37 6581.86,4950.04 v1(6573.52,4941.71) ; v1@6385.75,5148.49 cw(c6395.14,5139.1) 6395.14,5152.37 cw(c6395.14,5165.65) v1@6385.75,5156.26 ; v1@6388.57,5145.66 cw(c6404.79,5129.44) 6404.79,5152.37 cw(c6404.79,5175.31) v1@6388.57,5159.09 ; v1@6566.81,4948.43 ccw(c6530.47,4984.76) 6581.86,4984.76 ; v1@6569.64,4945.6 ccw(c6540.13,4975.1) 6581.86,4975.1 ; v1@6572.46,4942.77 ccw(c6549.79,4965.45) 6581.86,4965.45 ; v1@6575.29,4939.94 ccw(c6559.44,4955.79) 6581.86,4955.79 ; 5455.94,4492.16 cw(c5468.74,4479.35) 5468.74,4497.46 ccw(c5468.74,4479.35) 5455.94,4492.16 ; 5455.94,4492.16 ccw(c5443.13,4504.96) 5461.24,4504.96 cw(c5443.13,4504.96) 5455.94,4492.16
  MidLayer1 w4: v3@5468.09,4512.43 ccw(c5466.51,4530.47) 5480.38,4518.83 ; v3@5476.21,4505.61 cw(c5494.25,4507.19) 5480.38,4518.83 ; 5492.6,4581.77 5492.6,4567.84 ; v1@6375.14,5145.66 ccw(c6358.92,5129.44) 6358.92,5152.37 ccw(c6358.92,5175.31) v1@6375.14,5159.09 ; v1@6377.97,5148.49 ccw(c6368.58,5139.1) 6368.58,5152.37 ccw(c6368.58,5165.65) v1@6377.97,5156.26 ; v1(6381.86,5152.37) 5874.82,5152.37 5755.82,5033.37 5637.82,5033.37 5613.32,5008.88 5548.52,4944.08 5548.52,4861.35 5499.52,4812.35 5499.52,4795.08 5492.6,4788.16 5492.6,4724.74 5492.6,4720 5492.6,4710 5492.6,4661.38 5492.6,4641.96 5492.6,4567.84 ; 5480.38,4518.83 ccw(c5450.87,4548.34) 5492.6,4548.34 5492.6,4567.84
  Bottom Layer w4: v1@6566.81,4934.99 cw(c6550.59,4918.77) 6573.52,4918.77 cw(c6596.46,4918.77) v1@6580.24,4934.99 ; v1@6569.64,4937.82 cw(c6560.25,4928.43) 6573.52,4928.43 cw(c6586.8,4928.43) v1@6577.41,4937.82 ; v1(6573.52,4941.71) 6573.52,4915.72 6581.52,4907.72 U14.3@6619.41,4907.72 ; U14.3@6596.19,4902.06 ccw(c6582.54,4888.4) 6582.54,4907.72 ccw(c6582.54,4927.03) U14.3@6596.19,4913.37
DB_SRAM1.A3: U8.G17 U14.4 | length 1921.6
  Top Layer w4: U8.G17@5527.8,4445.91 v3(5547.48,4465.59) ; U8.G17@5527.8,4453.25 ccw(c5527.8,4470.97) 5540.33,4458.44 ccw(c5552.86,4445.91) U8.G17@5535.14,4445.91 ; U8.G17@5527.8,4453.41 ccw(c5527.8,4471.51) 5540.6,4458.71 ccw(c5553.4,4445.91) U8.G17@5535.3,4445.91 ; 5534.68,4452.79 cw(c5547.48,4439.98) 5547.48,4458.09 ccw(c5547.48,4439.98) 5534.68,4452.79 ; 5534.68,4452.79 ccw(c5521.87,4465.59) 5539.98,4465.59 cw(c5521.87,4465.59) 5534.68,4452.79
  MidLayer2 w4: v3@5546.83,4473.06 ccw(c5545.25,4491.1) 5559.12,4479.46 ccw(c5572.99,4467.82) v3@5554.95,4466.24 ; 5558.87,4479.17 ccw(c5548.94,4489.1) 5562.99,4489.1 ; 5562.99,4503.03 5562.99,4489.1 ; 5562.99,4699.16 5562.99,4640.9 ; v1@6564.02,4866.71 cw(c6541.09,4866.71) 6557.31,4850.49 cw(c6573.52,4834.27) v1@6573.52,4857.21 ; v1@6568.02,4866.71 cw(c6554.75,4866.71) 6564.14,4857.32 cw(c6573.52,4847.93) v1@6573.52,4861.21 ; v1(6573.52,4866.71) 6531.86,4825.04 6418.19,4825.04 6368.52,4775.37 6307.19,4775.37 6273.52,4741.71 6175.52,4741.71 6137.23,4780 6105,4780 6093.37,4768.37 6062.84,4768.37 5947.84,4883.37 5854.86,4883.37 5838.19,4900.04 5711.5,4900.04 5611.46,4800 5570,4800 5562.99,4792.99 5562.99,4724.74 5562.99,4720 5562.99,4710 5562.99,4640.9 ; 5562.99,4489.1 5562.99,4582.64 5562.99,4640.9
  Bottom Layer w4: v1(6573.52,4866.71) 6581.19,4866.71 6590.7,4876.22 ; v1@6576.41,4871.39 ccw(c6580.98,4878.79) 6587.12,4872.64 ; v1@6578.51,4874.79 ccw(c6583.7,4883.21) 6590.7,4876.22 ; v1@6580.82,4866.34 cw(c6596.41,4850.75) U14.4@6601.01,4872.31 ; 6586.02,4871.54 cw(c6598.24,4859.32) U14.4@6601.85,4876.22 ; 6591.22,4876.74 cw(c6600.07,4867.89) U14.4@6602.69,4880.13 ; U14.4@6619.41,4876.22 6590.7,4876.22
DB_SRAM1.A4: U8.B19 U14.5 | length 1958.6
  Top Layer w4: U8.B19@5606.54,4650.1 ccw(c5606.54,4667.83) 5619.07,4655.29 ; U8.B19@5613.88,4642.76 cw(c5631.6,4642.76) 5619.07,4655.29 ; 5622.04,4724.74 5622.04,4725.04 ; v1@5665.19,5107.21 cw(c5665.19,5084.27) 5681.41,5100.49 cw(c5697.63,5116.71) v1@5674.69,5116.71 ; v1@5665.19,5111.21 cw(c5665.19,5097.93) 5674.58,5107.32 cw(c5683.97,5116.71) v1@5670.69,5116.71 ; v1(5665.19,5116.71) 5681.69,5100.21 5681.69,4875.37 5648.52,4842.21 5648.52,4819.37 5613.86,4784.71 5613.86,4750.04 5622.04,4741.85 5622.04,4720 5622.04,4710 5622.04,4662.47 cw(c5611.89,4662.47) 5619.07,4655.29
  MidLayer2 w4: v1(5665.19,5116.71) 5665.19,5125.04 5681.86,5141.71 ; v1@5666.67,5116.97 cw(c5682.16,5119.75) 5671.03,5130.88 ; v1@5670.6,5117.68 cw(c5691.34,5121.4) 5676.44,5136.29 ; v1@5674.54,5118.39 cw(c5700.52,5123.05) 5681.86,5141.71 ; v1@6516.81,4959.99 ccw(c6500.59,4943.77) 6500.59,4966.71 ccw(c6500.59,4989.64) v1@6516.81,4973.43 ; v1@6519.64,4962.82 ccw(c6510.25,4953.43) 6510.25,4966.71 ccw(c6510.25,4979.99) v1@6519.64,4970.6 ; v1(6523.52,4966.71) 6415.19,4966.71 6265.19,5116.71 5898.52,5116.71 5890.19,5108.37 5763.86,5108.37 5730.52,5141.71 5681.86,5141.71
  Bottom Layer w4: v1@6523.52,4957.21 cw(c6523.52,4934.27) 6539.74,4950.49 cw(c6555.96,4966.71) v1@6533.02,4966.71 ; v1@6523.52,4961.21 cw(c6523.52,4947.93) 6532.91,4957.32 cw(c6542.3,4966.71) v1@6529.02,4966.71 ; v1(6523.52,4966.71) 6548.52,4941.71 6548.52,4928.37 6548.52,4920 6548.52,4858.37 6565.19,4841.71 6601.84,4841.71 6601.84,4844.72 U14.5@6619.41,4844.72 ; 6575.26,4841.71 ccw(c6575.26,4871.31) U14.5@6596.19,4850.38 ; 6584.91,4841.71 ccw(c6584.91,4861.66) U14.5@6599.02,4847.55 ; 6589.82,4841.71 cw(c6589.82,4832.69) U14.5@6596.19,4839.07
DB_SRAM1.A5: U8.K21 U14.18 | length 1451.8
  Top Layer w4: U8.K21@5685.28,4327.8 v3(5704.96,4347.48) ; U8.K21@5685.28,4335.14 ccw(c5685.28,4352.86) 5697.81,4340.33 ccw(c5710.34,4327.8) U8.K21@5692.62,4327.8 ; U8.K21@5685.28,4335.3 ccw(c5685.28,4353.4) 5698.08,4340.6 ccw(c5710.88,4327.8) U8.K21@5692.78,4327.8 ; 5692.16,4334.68 cw(c5704.96,4321.87) 5704.96,4339.98 ccw(c5704.96,4321.87) 5692.16,4334.68 ; 5692.16,4334.68 ccw(c5679.35,4347.48) 5697.46,4347.48 cw(c5679.35,4347.48) 5692.16,4334.68
  MidLayer1 w4: v3@5705.61,4354.95 ccw(c5707.19,4372.99) 5718.83,4359.12 ; v3@5712.43,4346.83 cw(c5730.47,4345.25) 5718.83,4359.12 ; 5781.77,4371.34 5767.84,4371.34 ; v1@6655.69,4483.37 ccw(c6632.76,4483.37) 6648.97,4499.59 ccw(c6665.19,4515.81) v1@6665.19,4492.87 ; v1@6659.69,4483.37 ccw(c6646.41,4483.37) 6655.8,4492.76 ccw(c6665.19,4502.15) v1@6665.19,4488.87 ; v1(6665.19,4483.37) 6631.86,4516.71 6556.71,4516.71 6545,4505 6501.71,4505 6490,4516.71 6220.54,4516.71 6111.88,4408.04 6095.21,4408.04 6075.88,4388.71 5978.79,4388.71 5961.43,4371.34 5920,4371.34 5910,4371.34 5861.38,4371.34 5841.96,4371.34 5767.84,4371.34 ; 5718.83,4359.12 cw(c5748.34,4329.61) 5748.34,4371.34 5767.84,4371.34
  Bottom Layer w4: U14.18@6619.41,4435.27 6660.27,4435.27 6665.19,4440.19 v1(6665.19,4483.37) ; U14.18@6642.63,4429.62 cw(c6656.28,4415.96) 6656.28,4435.27 cw(c6656.28,4454.59) U14.18@6642.63,4440.93 ; v1@6658.47,4476.66 cw(c6642.26,4460.44) 6665.19,4460.44 cw(c6688.13,4460.44) v1@6671.91,4476.66 ; v1@6661.3,4479.49 cw(c6651.91,4470.1) 6665.19,4470.1 cw(c6678.47,4470.1) v1@6669.08,4479.49
DB_SRAM1.A6: U8.K23 U14.19 | length 1381.3
  Top Layer w4: U8.K23@5764.02,4327.8 v3(5783.7,4347.48) ; U8.K23@5764.02,4335.14 ccw(c5764.02,4352.86) 5776.55,4340.33 ccw(c5789.08,4327.8) U8.K23@5771.36,4327.8 ; U8.K23@5764.02,4335.3 ccw(c5764.02,4353.4) 5776.82,4340.6 ccw(c5789.62,4327.8) U8.K23@5771.52,4327.8 ; 5770.9,4334.68 cw(c5783.7,4321.87) 5783.7,4339.98 ccw(c5783.7,4321.87) 5770.9,4334.68 ; 5770.9,4334.68 ccw(c5758.09,4347.48) 5776.2,4347.48 cw(c5758.09,4347.48) 5770.9,4334.68
  MidLayer1 w4: v3(5783.7,4347.48) 5861.38,4347.48 5910,4347.48 5920,4347.48 5976.13,4347.48 5981.9,4341.71 6137.21,4341.71 6253.88,4458.37 6323.52,4458.37 6348.52,4433.37 6565.19,4433.37 v1(6573.52,4425.04) ; v3@5788.89,4342.29 cw(c5801.43,4329.75) 5801.43,4347.48 cw(c5801.43,4365.21) v3@5788.89,4352.67 ; 6530.47,4433.37 cw(c6530.47,4381.99) v1@6566.81,4418.32 ; 6540.13,4433.37 cw(c6540.13,4391.64) v1@6569.64,4421.15 ; 6549.78,4433.37 cw(c6549.78,4401.3) v1@6572.46,4423.98 ; 6559.44,4433.37 cw(c6559.44,4410.96) v1@6575.29,4426.81 ; 5801.81,4347.48 cw(c5801.81,4365.59) 5789,4352.78 ccw(c5801.81,4365.59) 5801.81,4347.48 ; 5801.81,4347.48 ccw(c5801.81,4329.37) 5789,4342.18 cw(c5801.81,4329.37) 5801.81,4347.48
  Bottom Layer w4: v1@6573.52,4415.54 cw(c6573.52,4392.61) 6589.74,4408.82 cw(c6605.96,4425.04) v1@6583.02,4425.04 ; v1@6573.52,4419.54 cw(c6573.52,4406.26) 6582.91,4415.65 cw(c6592.3,4425.04) v1@6579.02,4425.04 ; v1(6573.52,4425.04) 6598.52,4400.04 6619.41,4400.04 6623.52,4400.04 6623.52,4403.78 U14.19@6619.41,4403.78 ; v1@6577.06,4421.51 ccw(c6600.59,4445.04) U14.19@6601.61,4411.77 ; 6583.6,4414.96 ccw(c6600.98,4432.34) U14.19@6601.73,4407.78 ; 6590.15,4408.42 ccw(c6601.37,4419.64) U14.19@6601.85,4403.78
DB_SRAM1.A7: U8.L9 U14.20 | length 4775.9
  Top Layer w4: v3(5193.15,4308.11) U8.L9@5212.83,4288.43 ; U8.L9@5205.33,4288.43 ccw(c5187.23,4288.43) 5200.03,4301.23 ccw(c5212.83,4314.03) U8.L9@5212.83,4295.93 ; U8.L9@5205.49,4288.43 ccw(c5187.77,4288.43) 5200.3,4300.96 ccw(c5212.83,4313.49) U8.L9@5212.83,4295.77 ; 5205.95,4295.31 ccw(c5193.15,4282.5) 5193.15,4300.61 cw(c5193.15,4282.5) 5205.95,4295.31 ; 5205.95,4295.31 cw(c5218.76,4308.11) 5200.65,4308.11 ccw(c5218.76,4308.11) 5205.95,4295.31
  MidLayer2 w4: v1(4615.19,4354.04) 4653.19,4392.04 4653.19,4563.71 4640.19,4576.71 4640.19,4685 ; v1@4615.19,4359.54 ccw(c4615.19,4372.82) 4624.58,4363.43 ccw(c4633.97,4354.04) v1@4620.69,4354.04 ; v1@4615.19,4363.54 ccw(c4615.19,4386.48) 4631.41,4370.26 ccw(c4647.63,4354.04) v1@4624.69,4354.04 ; 4640,4685 4628.52,4696.48 4628.52,5035 4822.71,5229.19 5092.33,5229.19 5104.98,5216.54 5193.73,5216.54 5252.4,5157.87 5292.87,5157.87 5372.37,5237.37 5646.19,5237.37 5675.19,5208.37 6584.71,5208.37 6638.02,5155.06 6638.02,4920.83 6683.86,4875 v1(6683.86,4802.04) ; v1@6677.14,4808.76 ccw(c6660.92,4824.98) 6683.86,4824.98 ccw(c6706.79,4824.98) v1@6690.57,4808.76 ; v1@6679.97,4805.93 ccw(c6670.58,4815.32) 6683.86,4815.32 ccw(c6697.14,4815.32) v1@6687.75,4805.93
  Bottom Layer w4: v1@4615.19,4344.54 cw(c4615.19,4321.61) 4631.41,4337.82 cw(c4647.63,4354.04) v1@4624.69,4354.04 ; v1@4615.19,4348.54 cw(c4615.19,4335.26) 4624.58,4344.65 cw(c4633.97,4354.04) v1@4620.69,4354.04 ; v1(4615.19,4354.04) 4645.19,4324.04 4765.19,4324.04 4767.52,4326.37 4811.06,4326.37 4813.82,4323.62 4860,4323.62 4870,4323.62 5076.1,4323.62 5169.64,4323.62 cw(c5169.64,4309.57) 5179.57,4319.5 ; v3@5185.68,4307.46 ccw(c5167.64,4305.88) 5179.28,4319.75 ccw(c5190.92,4333.62) v3@5192.5,4315.58 ; U14.20@6619.41,4372.28 6677.28,4372.28 6695,4390 6695,4468.18 6716.52,4489.71 6716.52,4666.71 6701.52,4681.71 6666.86,4681.71 6656.86,4691.71 6656.86,4766.71 6683.86,4793.71 v1(6683.86,4802.04) ; U14.20@6642.63,4366.63 cw(c6656.28,4352.97) 6656.28,4372.28 cw(c6656.28,4391.6) U14.20@6642.63,4377.94
DB_SRAM1.A8: U8.M18 U14.21 | length 1526.3
  Top Layer w4: U8.M18@5567.17,4249.06 v3(5586.85,4268.74) ; U8.M18@5567.17,4256.4 ccw(c5567.17,4274.12) 5579.7,4261.59 ccw(c5592.23,4249.06) U8.M18@5574.51,4249.06 ; U8.M18@5567.17,4256.56 ccw(c5567.17,4274.66) 5579.97,4261.86 ccw(c5592.77,4249.06) U8.M18@5574.67,4249.06 ; 5574.05,4255.94 cw(c5586.85,4243.13) 5586.85,4261.24 ccw(c5586.85,4243.13) 5574.05,4255.94 ; 5574.05,4255.94 ccw(c5561.24,4268.74) 5579.35,4268.74 cw(c5561.24,4268.74) 5574.05,4255.94
  MidLayer1 w4: v1(6008.19,4286.37) 6027.86,4306.04 6069.21,4306.04 6073.86,4301.39 6073.86,4275.37 6073.52,4275.04 6090.19,4258.37 6165.19,4258.37 6198.52,4291.71 6198.52,4316.71 6209.52,4327.71 6237.52,4327.71 6256.86,4308.37 6298.52,4308.37 6315.19,4325.04 6465.86,4325.04 v1(6482.52,4341.71) ; v1@6008.19,4291.87 ccw(c6008.19,4305.15) 6017.58,4295.76 ccw(c6026.97,4286.37) v1@6013.69,4286.37 ; v1@6008.19,4295.87 ccw(c6008.19,4318.81) 6024.41,4302.59 ccw(c6040.63,4286.37) v1@6017.69,4286.37 ; v1@6473.02,4341.71 cw(c6450.09,4341.71) 6466.31,4325.49 cw(c6482.52,4309.27) v1@6482.52,4332.21 ; v1@6477.02,4341.71 cw(c6463.75,4341.71) 6473.14,4332.32 cw(c6482.52,4322.93) v1@6482.52,4336.21
  Bottom Layer w4: v3@5587.5,4276.21 ccw(c5589.08,4294.25) 5600.72,4280.38 ccw(c5612.36,4266.51) v3@5594.32,4268.09 ; 5600.43,4280.13 cw(c5610.36,4270.2) 5610.36,4284.25 5703.9,4284.25 5910,4284.25 5920,4284.25 5924.74,4284.25 5990.06,4284.25 5992.19,4286.37 ; v1@5999.85,4281.83 ccw(c5992.19,4277.65) 5992.19,4286.37 ; v1@5999.85,4290.92 cw(c5992.19,4295.1) 5992.19,4286.37 ; v1(6008.19,4286.37) 5992.19,4286.37 ; v1(6482.52,4341.71) 6526.71,4341.71 6535,4350 6570,4350 6579.21,4340.79 U14.21@6619.41,4340.79 ; v1@6486.41,4337.82 cw(c6495.8,4328.43) 6495.8,4341.71 cw(c6495.8,4354.99) v1@6486.41,4345.6 ; v1@6489.24,4334.99 cw(c6505.46,4318.77) 6505.46,4341.71 cw(c6505.46,4364.64) v1@6489.24,4348.43 ; U14.21@6596.19,4335.13 ccw(c6582.54,4321.47) 6582.54,4340.79 ccw(c6582.54,4360.1) U14.21@6596.19,4346.44
DB_SRAM1.A9: U8.N9 U14.22 | length 6640.4
  Top Layer w4: v1(4231.86,4358.37) 4256.86,4383.37 4256.86,4821.86 4280,4845 4280,4923.18 4286.4,4929.58 4298.52,4941.71 4298.52,4991.71 v1(4398.52,5091.71) ; v1@4231.86,4363.87 ccw(c4231.86,4377.15) 4241.25,4367.76 ccw(c4250.64,4358.37) v1@4237.36,4358.37 ; v1@4231.86,4367.87 ccw(c4231.86,4390.81) 4248.07,4374.59 ccw(c4264.29,4358.37) v1@4241.36,4358.37 ; v1@4389.02,5091.71 cw(c4366.09,5091.71) 4382.31,5075.49 cw(c4398.52,5059.27) v1@4398.52,5082.21 ; v1@4393.02,5091.71 cw(c4379.75,5091.71) 4389.14,5082.32 cw(c4398.52,5072.93) v1@4398.52,5086.21 ; v3(5193.15,4229.37) U8.N9@5212.83,4209.69 ; U8.N9@5205.33,4209.69 ccw(c5187.23,4209.69) 5200.03,4222.49 ccw(c5212.83,4235.29) U8.N9@5212.83,4217.19 ; U8.N9@5205.49,4209.69 ccw(c5187.77,4209.69) 5200.3,4222.22 ccw(c5212.83,4234.75) U8.N9@5212.83,4217.03 ; 5205.95,4216.57 ccw(c5193.15,4203.76) 5193.15,4221.87 cw(c5193.15,4203.76) 5205.95,4216.57 ; 5205.95,4216.57 cw(c5218.76,4229.37) 5200.65,4229.37 ccw(c5218.76,4229.37) 5205.95,4216.57
  MidLayer2 w4: v1@4398.52,5082.21 cw(c4398.52,5059.27) 4414.74,5075.49 cw(c4430.96,5091.71) v1@4408.02,5091.71 ; v1@4398.52,5086.21 cw(c4398.52,5072.93) 4407.91,5082.32 cw(c4417.3,5091.71) v1@4404.02,5091.71 ; v1(4398.52,5091.71) 4423.52,5066.71 4552.19,5066.71 4706.86,5221.37 4706.86,5235 4776.86,5305 5025,5305 5060,5340 5320,5340 5365.37,5385.37 5819.63,5385.37 5850,5355 5923.87,5355 6046.5,5232.37 6594.65,5232.37 6662.02,5165 6662.02,4930.77 6668.42,4924.37 6705.63,4924.37 6716.25,4935 6742.29,4935 6750.04,4927.25 6796.42,4880.87 6806.09,4880.87 6841.75,4845.21 6955.02,4845.21 v1(6974.19,4826.04) ; v1@6964.69,4826.04 ccw(c6941.76,4826.04) 6957.97,4842.26 ccw(c6974.19,4858.48) v1@6974.19,4835.54 ; v1@6968.69,4826.04 ccw(c6955.41,4826.04) 6964.8,4835.43 ccw(c6974.19,4844.82) v1@6974.19,4831.54
  Bottom Layer w4: v1@4231.86,4348.87 cw(c4231.86,4325.94) 4248.07,4342.16 cw(c4264.29,4358.37) v1@4241.36,4358.37 ; v1@4231.86,4352.87 cw(c4231.86,4339.6) 4241.25,4348.99 cw(c4250.64,4358.37) v1@4237.36,4358.37 ; v1(4231.86,4358.37) 4290.19,4300.04 4523.19,4300.04 4580.19,4243.04 4715.86,4243.04 4731.86,4227.04 4731.86,4183.37 4748.52,4166.71 4756.86,4166.71 4772.04,4151.52 4804.3,4151.52 4807.81,4155.03 4807.81,4185.06 4824.02,4201.27 4824.02,4241.22 4827.68,4244.88 4860,4244.88 4870,4244.88 5076.1,4244.88 5169.64,4244.88 cw(c5169.64,4230.83) 5179.57,4240.76 ; v3@5185.68,4228.72 ccw(c5167.64,4227.14) 5179.28,4241.01 ccw(c5190.92,4254.88) v3@5192.5,4236.84 ; U14.22@6619.41,4309.29 6626.99,4301.71 6641.99,4301.71 6641.99,4286.71 6677.99,4250.71 6911.19,4250.71 6943.52,4283.04 6943.52,4308.37 6969.61,4334.46 7020.63,4334.46 7073.52,4387.36 7073.52,4635.04 6974.19,4734.37 v1(6974.19,4826.04) ; U14.22@6632.82,4302.45 cw(c6622.93,4286.16) 6641.99,4286.16 ; U14.22@6634.89,4305.87 cw(c6627.24,4293.26) 6641.99,4293.26 ; U14.22@6636.97,4309.29 cw(c6631.55,4300.37) U14.22@6641.99,4300.37 ; v1@6967.47,4819.32 cw(c6951.26,4803.11) 6974.19,4803.11 cw(c6997.13,4803.11) v1@6980.91,4819.32 ; v1@6970.3,4822.15 cw(c6960.91,4812.76) 6974.19,4812.76 cw(c6987.47,4812.76) v1@6978.08,4822.15
DB_SRAM1.A10: U8.M20 U14.23 | length 866.9
  Top Layer w4: U8.M20@5645.91,4249.06 v3(5665.59,4268.74) ; U8.M20@5645.91,4256.4 ccw(c5645.91,4274.12) 5658.44,4261.59 ccw(c5670.97,4249.06) U8.M20@5653.25,4249.06 ; U8.M20@5645.91,4256.56 ccw(c5645.91,4274.66) 5658.71,4261.86 ccw(c5671.51,4249.06) U8.M20@5653.41,4249.06 ; 5652.79,4255.94 cw(c5665.59,4243.13) 5665.59,4261.24 ccw(c5665.59,4243.13) 5652.79,4255.94 ; 5652.79,4255.94 ccw(c5639.98,4268.74) 5658.09,4268.74 cw(c5639.98,4268.74) 5652.79,4255.94
  MidLayer2 w4: v3@5666.24,4276.21 ccw(c5667.82,4294.25) 5679.46,4280.38 ccw(c5691.1,4266.51) v3@5673.06,4268.09 ; 5679.17,4280.13 cw(c5689.1,4270.2) 5689.1,4284.25 5782.64,4284.25 5910,4284.25 5920,4284.25 5924.74,4284.25 5966.06,4284.25 5986.19,4304.37 6012.51,4304.37 6024.84,4316.71 6135,4316.71 6143.33,4308.37 v1(6217.19,4308.37) ; v1@6210.47,4301.66 ccw(c6194.26,4285.44) 6194.26,4308.37 ccw(c6194.26,4331.31) v1@6210.47,4315.09 ; v1@6213.3,4304.49 ccw(c6203.91,4295.1) 6203.91,4308.37 ccw(c6203.91,4321.65) v1@6213.3,4312.26
  Bottom Layer w4: U14.23@6170.59,4309.29 6202.11,4309.29 ; U14.23@6195.05,4305.25 cw(c6202.11,4301.12) 6202.11,4309.29 ; U14.23@6195.05,4313.33 ccw(c6202.11,4317.46) 6202.11,4309.29 ; v1@6208.85,4303.83 ccw(c6201.19,4299.65) 6201.19,4308.37 ; v1@6208.85,4312.92 cw(c6201.19,4317.1) 6201.19,4308.37 ; v1(6217.19,4308.37) 6201.19,4308.37 ; 6201.19,4308.37 6202.11,4309.29
DB_SRAM1.A11: U8.L18 U14.24 | length 778.2
  Top Layer w4: U8.L18@5567.17,4288.43 v3(5586.85,4308.11) ; U8.L18@5567.17,4295.77 ccw(c5567.17,4313.49) 5579.7,4300.96 ccw(c5592.23,4288.43) U8.L18@5574.51,4288.43 ; U8.L18@5567.17,4295.93 ccw(c5567.17,4314.03) 5579.97,4301.23 ccw(c5592.77,4288.43) U8.L18@5574.67,4288.43 ; 5574.05,4295.31 cw(c5586.85,4282.5) 5586.85,4300.61 ccw(c5586.85,4282.5) 5574.05,4295.31 ; 5574.05,4295.31 ccw(c5561.24,4308.11) 5579.35,4308.11 cw(c5561.24,4308.11) 5574.05,4295.31
  Bottom Layer w4: v3@5587.5,4315.58 ccw(c5589.08,4333.62) 5600.72,4319.75 ccw(c5612.36,4305.88) v3@5594.32,4307.46 ; 5600.43,4319.5 cw(c5610.36,4309.57) 5610.36,4323.62 5703.9,4323.62 5910,4323.62 5920,4323.62 6100.08,4323.62 6117.25,4340.79 U14.24@6170.59,4340.79 ; U14.24@6147.37,4335.13 ccw(c6133.72,4321.47) 6133.72,4340.79 ccw(c6133.72,4360.1) U14.24@6147.37,4346.44
DB_SRAM1.A12: U8.L17 U14.25 | length 817.4
  Top Layer w4: U8.L17@5527.8,4288.43 v3(5547.48,4308.11) ; U8.L17@5527.8,4295.77 ccw(c5527.8,4313.49) 5540.33,4300.96 ccw(c5552.86,4288.43) U8.L17@5535.14,4288.43 ; U8.L17@5527.8,4295.93 ccw(c5527.8,4314.03) 5540.6,4301.23 ccw(c5553.4,4288.43) U8.L17@5535.3,4288.43 ; 5534.68,4295.31 cw(c5547.48,4282.5) 5547.48,4300.61 ccw(c5547.48,4282.5) 5534.68,4295.31 ; 5534.68,4295.31 ccw(c5521.87,4308.11) 5539.98,4308.11 cw(c5521.87,4308.11) 5534.68,4295.31
  Bottom Layer w4: v3@5548.13,4315.58 ccw(c5549.71,4333.62) 5561.35,4319.75 ; v3@5554.95,4307.46 cw(c5572.99,4305.88) 5561.35,4319.75 ; 6140.38,4375.04 ccw(c6140.38,4384.94) U14.25@6147.37,4377.94 ; U14.25@6145.16,4370.88 ccw(c6140.19,4370) 6140.19,4375.04 ; U14.25@6170.59,4372.28 6165.19,4372.28 6165.19,4375.04 6140.19,4375.04 ; 5561.35,4319.75 cw(c5590.86,4290.24) 5590.86,4331.97 5610.36,4331.97 5684.48,4331.97 5703.9,4331.97 5910,4331.97 5920,4331.97 6097.12,4331.97 6108.17,4343.02 6140.19,4375.04
DB_SRAM1.A13: U8.J23 U14.26 | length 781.7
  Top Layer w4: U8.J23@5764.02,4367.17 v3(5783.7,4386.85) ; U8.J23@5764.02,4374.51 ccw(c5764.02,4392.23) 5776.55,4379.7 ccw(c5789.08,4367.17) U8.J23@5771.36,4367.17 ; U8.J23@5764.02,4374.67 ccw(c5764.02,4392.77) 5776.82,4379.97 ccw(c5789.62,4367.17) U8.J23@5771.52,4367.17 ; 5770.9,4374.05 cw(c5783.7,4361.24) 5783.7,4379.35 ccw(c5783.7,4361.24) 5770.9,4374.05 ; 5770.9,4374.05 ccw(c5758.09,4386.85) 5776.2,4386.85 cw(c5758.09,4386.85) 5770.9,4374.05
  MidLayer1 w4: v3(5783.7,4386.85) 5861.38,4386.85 5910,4386.85 5920,4386.85 5965.14,4386.85 5975,4396.71 6047.52,4396.71 v1(6075.86,4425.04) ; v3@5788.89,4381.66 cw(c5801.43,4369.12) 5801.43,4386.85 cw(c5801.43,4404.58) v3@5788.89,4392.04 ; v3@5789,4381.55 cw(c5801.81,4368.74) 5801.81,4386.85 cw(c5801.81,4404.96) v3@5789,4392.15 ; v1@6066.36,4425.04 cw(c6043.42,4425.04) 6059.64,4408.82 cw(c6075.86,4392.61) v1@6075.86,4415.54 ; v1@6070.36,4425.04 cw(c6057.08,4425.04) 6066.47,4415.65 cw(c6075.86,4406.26) v1@6075.86,4419.54
  Bottom Layer w4: v1@6075.86,4415.54 cw(c6075.86,4392.61) 6092.07,4408.82 cw(c6108.29,4425.04) v1@6085.36,4425.04 ; v1@6075.86,4419.54 cw(c6075.86,4406.26) 6085.25,4415.65 cw(c6094.64,4425.04) v1@6081.36,4425.04 ; v1(6075.86,4425.04) 6100.86,4400.04 6170.59,4400.04 6173.52,4400.04 6173.52,4403.78 U14.26@6170.59,4403.78 ; 6124.69,4400.04 ccw(c6124.69,4432.12) U14.26@6147.37,4409.44 ; 6134.35,4400.04 ccw(c6134.35,4422.46) U14.26@6150.2,4406.61 ; 6142.74,4400.04 cw(c6142.74,4393.49) U14.26@6147.37,4398.12
DB_SRAM1.A14: U8.J19 U14.27 | length 853.2
  Top Layer w4: U8.J19@5606.54,4367.17 v3(5626.22,4386.85) ; U8.J19@5606.54,4374.51 ccw(c5606.54,4392.23) 5619.07,4379.7 ccw(c5631.6,4367.17) U8.J19@5613.88,4367.17 ; U8.J19@5606.54,4374.67 ccw(c5606.54,4392.77) 5619.34,4379.97 ccw(c5632.14,4367.17) U8.J19@5614.04,4367.17 ; 5613.42,4374.05 cw(c5626.22,4361.24) 5626.22,4379.35 ccw(c5626.22,4361.24) 5613.42,4374.05 ; 5613.42,4374.05 ccw(c5600.61,4386.85) 5618.72,4386.85 cw(c5600.61,4386.85) 5613.42,4374.05
  MidLayer2 w4: v3@5627.52,4394.24 ccw(c5630.67,4412.07) 5641.05,4397.24 ; v3@5633.61,4385.55 cw(c5651.44,4382.4) 5641.05,4397.24 ; v1@6109.19,4442.68 cw(c6098.89,4430.04) 6115.19,4430.04 ; v1@6111.72,4445.78 cw(c6105.75,4438.46) 6115.19,4438.46 cw(c6124.63,4438.46) v1@6118.67,4445.78 ; v1(6115.19,4450.04) 6115.19,4430.04 ; v1@6121.19,4442.68 ccw(c6131.49,4430.04) 6115.19,4430.04 ; 5641.05,4397.24 5649.63,4404.32 cw(c5665.85,4386.94) 5665.85,4410.71 5689.1,4410.71 5763.22,4410.71 5782.64,4410.71 5910,4410.71 5920,4410.71 5935.71,4410.71 5939,4414 5939,4430.71 5950,4441.71 5995.52,4441.71 6020.52,4416.71 6046.15,4416.71 6057.48,4405.37 6090.52,4405.37 6115.19,4430.04
  Bottom Layer w4: v1(6115.19,4450.04) 6129.96,4435.27 U14.27@6170.59,4435.27 ; U14.27@6147.37,4429.62 ccw(c6133.72,4415.96) 6133.72,4435.27 ccw(c6133.72,4454.59) U14.27@6147.37,4440.93
DB_SRAM1.A15: U8.B15 U14.42 | length 1420.9
  Top Layer w4: U8.B15@5449.06,4650.1 ccw(c5449.06,4667.83) 5461.59,4655.29 ; v1@5455.5,4935 cw(c5432.56,4935) 5448.78,4918.78 cw(c5465,4902.56) v1@5465,4925.5 ; U8.B15@5456.4,4642.76 cw(c5474.12,4642.76) 5461.59,4655.29 ; v1@5459.5,4935 cw(c5446.22,4935) 5455.61,4925.61 cw(c5465,4916.22) v1@5465,4929.5 ; v1(5465,4935) 5430.5,4900.5 5430.5,4840 5430.5,4813.04 5464.56,4778.98 5464.56,4770 5464.56,4763 5464.56,4724.74 5464.56,4720 5464.56,4710 5464.56,4662.47 cw(c5454.41,4662.47) 5461.59,4655.29
  Bottom Layer w4: v1(5465,4935) 5465,4934.85 5513.86,4983.71 5703,4983.71 5795,4891.71 5838.86,4891.71 5922.19,4808.37 5982.86,4808.37 6023.52,4849.04 6023.52,4899.37 6048.52,4924.37 6090,4924.37 6106.66,4907.72 U14.42@6170.59,4907.72 6136.7,4907.72 ; v1@5465,4940.5 ccw(c5465,4954.14) 5474.64,4944.49 ; v1@5465,4944.5 ccw(c5465,4967.8) 5481.47,4951.32 ; v1@5470.5,4935 cw(c5483.42,4935) 5474.28,4944.13 ; v1@5474.5,4935 cw(c5497.07,4935) 5481.11,4950.96 ; U14.42@6146.71,4902.81 ccw(c6136.7,4895.04) 6136.7,4907.72 ccw(c6136.7,4920.39) U14.42@6146.71,4912.62 ; U14.42@6147.37,4902.06 ccw(c6133.72,4888.4) 6133.72,4907.72 ccw(c6133.72,4927.03) U14.42@6147.37,4913.37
